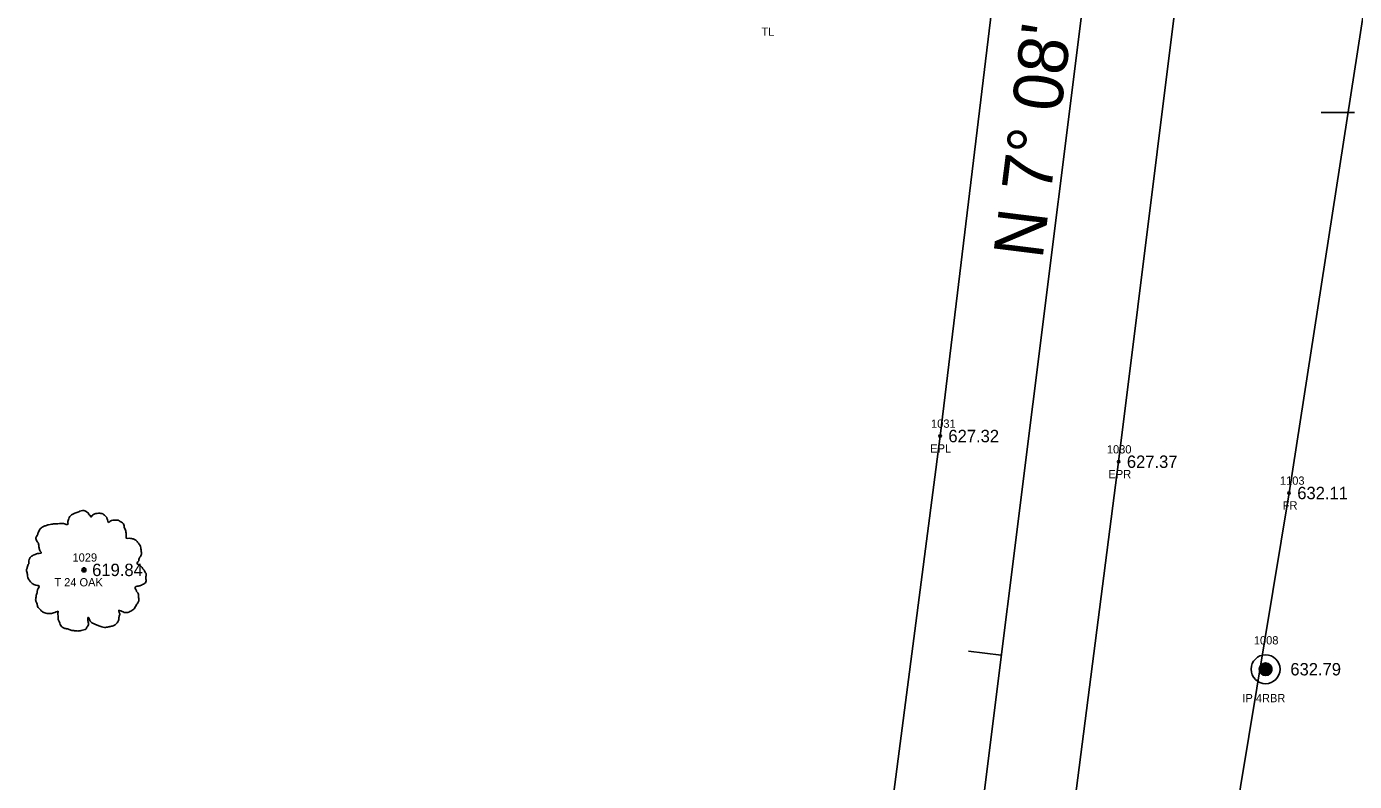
# Model space of a CAD drawing. Extents: x 1694813 to 1696862, y 1086485 to 1091027.
# Drawn here: x 1695761.1 to 1695921.9, y 1087627 to 1087718.4 of the extents above; entities that cross this region are included whole.
import ezdxf

# ---------------------------------------------------------------- set-up
doc = ezdxf.new("R2010")
doc.units = 0
for name, color, linetype in [('RD_EX_DV_Prop_txCode', 7, 'Continuous'), ('RD_EX_DV_PropPin', 7, 'Continuous'), ('RD_EX_Fence_Other', 7, 'Continuous'), ('RD_EX_Fence_Other_txCode', 7, 'Continuous'), ('RD_EX_Road', 7, 'Continuous'), ('RD_EX_Road_txCode', 7, 'Continuous'), ('RD_EX_TX_DV_Prop_ELEV', 7, 'Continuous'), ('RD_EX_TX_Fence_Other_ELEV', 7, 'Continuous'), ('RD_EX_TX_Road_ELEV', 7, 'Continuous'), ('RD_EX_TX_VEG_ELEV', 7, 'Continuous'), ('RD_EX_UT', 7, 'Continuous'), ('RD_EX_VEG', 7, 'Continuous'), ('RD_EX_VEG_txCode', 7, 'Continuous'), ('RD_HC_Cl', 7, 'Continuous'), ('RD_HC_Data', 7, 'Continuous'), ('RD_HC_Data_Tic', 7, 'Continuous'), ('RD_SMD_Locator', 7, 'Continuous')]:
    doc.layers.add(name, color=color, linetype=linetype)

msp = doc.modelspace()

# ---------------------------------------------------------------- linework, layer by layer
at = {"layer": 'RD_EX_DV_PropPin'}
for p, q in [((1695911.03, 1087639.83), (1695911.03, 1087641.34)), ((1695911.06, 1087639.83), (1695911.06, 1087641.34)), ((1695911.1, 1087639.82), (1695911.1, 1087641.34)), ((1695911.13, 1087639.82), (1695911.13, 1087641.34)), ((1695911.17, 1087639.82), (1695911.17, 1087641.34)), ((1695911.2, 1087639.83), (1695911.2, 1087641.34)), ((1695911.24, 1087639.83), (1695911.24, 1087641.34)), ((1695910.4, 1087640.39), (1695910.4, 1087640.78)), ((1695910.43, 1087640.29), (1695910.43, 1087640.88)), ((1695910.47, 1087640.21), (1695910.47, 1087640.95)), ((1695910.5, 1087640.16), (1695910.5, 1087641.01)), ((1695910.54, 1087640.11), (1695910.54, 1087641.06)), ((1695910.57, 1087640.07), (1695910.57, 1087641.1)), ((1695910.61, 1087640.03), (1695910.61, 1087641.13)), ((1695910.64, 1087640), (1695910.64, 1087641.17)), ((1695910.68, 1087639.97), (1695910.68, 1087641.19)), ((1695910.71, 1087639.95), (1695910.71, 1087641.22)), ((1695910.75, 1087639.93), (1695910.75, 1087641.24)), ((1695910.78, 1087639.91), (1695910.78, 1087641.26)), ((1695910.82, 1087639.89), (1695910.82, 1087641.28)), ((1695910.85, 1087639.88), (1695910.85, 1087641.29)), ((1695910.89, 1087639.86), (1695910.89, 1087641.3)), ((1695910.92, 1087639.85), (1695910.92, 1087641.32)), ((1695910.96, 1087639.84), (1695910.96, 1087641.32)), ((1695910.99, 1087639.84), (1695910.99, 1087641.33)), ((1695911.27, 1087639.84), (1695911.27, 1087641.33)), ((1695911.31, 1087639.84), (1695911.31, 1087641.32)), ((1695911.34, 1087639.85), (1695911.34, 1087641.32)), ((1695911.38, 1087639.86), (1695911.38, 1087641.3)), ((1695911.41, 1087639.88), (1695911.41, 1087641.29)), ((1695911.45, 1087639.89), (1695911.45, 1087641.28)), ((1695911.48, 1087639.91), (1695911.48, 1087641.26)), ((1695911.52, 1087639.93), (1695911.52, 1087641.24)), ((1695911.55, 1087639.95), (1695911.55, 1087641.22)), ((1695911.59, 1087639.97), (1695911.59, 1087641.19)), ((1695911.62, 1087640), (1695911.62, 1087641.17)), ((1695911.66, 1087640.03), (1695911.66, 1087641.13)), ((1695911.69, 1087640.07), (1695911.69, 1087641.1)), ((1695911.73, 1087640.11), (1695911.73, 1087641.06)), ((1695911.76, 1087640.16), (1695911.76, 1087641.01)), ((1695911.8, 1087640.21), (1695911.8, 1087640.95)), ((1695911.83, 1087640.29), (1695911.83, 1087640.88)), ((1695911.87, 1087640.39), (1695911.87, 1087640.78))]:
    msp.add_line(p, q, dxfattribs=at)
for radius in [1.75, 0.761]:
    msp.add_circle((1695911.13, 1087640.58), radius, dxfattribs=at)
at = {"layer": 'RD_EX_Fence_Other'}
msp.add_lwpolyline([(1695896.34, 1087555.36), (1695913.97, 1087661.92), (1695929.73, 1087763.6), (1695939.84, 1087832.07), (1696009.84, 1087821.33)], dxfattribs=at)
at = {"layer": 'RD_EX_Road'}
for points in [[(1695879.87, 1087561.29), (1695893.33, 1087665.71), (1695905.96, 1087767.16), (1695918.66, 1087869.54), (1695930.87, 1087972.82), (1695936.26, 1088023.68), (1695942.14, 1088076.32), (1695948.07, 1088128.17), (1695955.04, 1088181.4), (1695962.88, 1088230.72), (1695971.68, 1088284.64), (1695982.02, 1088336.12), (1695993.28, 1088388.48), (1696018.75, 1088494.48), (1696045.23, 1088599.95), (1696055.72, 1088654.41), (1696060.15, 1088705.35), (1696055.83, 1088758.02), (1696044.01, 1088812.16), (1696026.4, 1088860.33), (1696000.41, 1088911.48), (1695972.46, 1088953.82), (1695939.48, 1088998.73), (1695931.21, 1088992.88)], [(1695858.19, 1087564.9), (1695871.71, 1087668.82), (1695884.5, 1087774.69), (1695887.48, 1087794.2), (1695897.57, 1087873.43), (1695908.92, 1087975.76), (1695914.49, 1088029.24), (1695917.65, 1088054.8), (1695920.27, 1088079.09), (1695926.98, 1088130.26), (1695934.75, 1088185.09), (1695942.15, 1088234.62), (1695951.36, 1088288.06), (1695961.48, 1088338.41), (1695972.86, 1088394.13), (1695998.53, 1088499.67), (1696024.81, 1088603.86), (1696034.83, 1088656.78)]]:
    msp.add_lwpolyline(points, dxfattribs=at)
at = {"layer": 'RD_EX_UT'}
msp.add_line((1695921.88, 1087708.01), (1695917.88, 1087708.01), dxfattribs=at)
at = {"layer": 'RD_EX_VEG'}
for centre, radius in [((1695768, 1087652.61), 0.25), ((1695767.99, 1087652.6), 0.0001)]:
    msp.add_circle(centre, radius, dxfattribs=at)
for points in [[(1695768.13, 1087659.78), (1695767.83, 1087659.81), (1695767.51, 1087659.71), (1695767.26, 1087659.61), (1695767.03, 1087659.53), (1695766.81, 1087659.43), (1695766.51, 1087659.26), (1695766.28, 1087659.06), (1695766.16, 1087658.81), (1695766.11, 1087658.58), (1695766.06, 1087658.31), (1695766.06, 1087658.13), (1695765.93, 1087658.11), (1695765.78, 1087658.13), (1695765.53, 1087658.21), (1695765.28, 1087658.21), (1695765.03, 1087658.21), (1695764.68, 1087658.18), (1695764.33, 1087658.18), (1695764.06, 1087658.13), (1695763.73, 1087658.08), (1695763.36, 1087657.96), (1695763.01, 1087657.83), (1695762.71, 1087657.58), (1695762.46, 1087657.11), (1695762.34, 1087656.76), (1695762.19, 1087656.51), (1695762.34, 1087656.06), (1695762.51, 1087655.71), (1695762.54, 1087655.51), (1695762.61, 1087655.08), (1695762.71, 1087654.86), (1695762.84, 1087654.66), (1695762.76, 1087654.63), (1695762.39, 1087654.58), (1695762.09, 1087654.48), (1695761.66, 1087654.26), (1695761.44, 1087654.03), (1695761.34, 1087653.71), (1695761.31, 1087653.36), (1695761.21, 1087653.16), (1695761.14, 1087652.88), (1695761.11, 1087652.81), (1695761.06, 1087652.49), (1695761.16, 1087652.04), (1695761.19, 1087651.69), (1695761.31, 1087651.46), (1695761.46, 1087651.29), (1695761.64, 1087651.04), (1695762.04, 1087650.81), (1695762.36, 1087650.71), (1695762.56, 1087650.69), (1695762.39, 1087650.19), (1695762.34, 1087649.84), (1695762.21, 1087649.44), (1695762.21, 1087649.36), (1695762.16, 1087648.89), (1695762.31, 1087648.56), (1695762.39, 1087648.19), (1695762.56, 1087647.96), (1695762.84, 1087647.66), (1695763.16, 1087647.44), (1695763.66, 1087647.31), (1695764.06, 1087647.34), (1695764.63, 1087647.51), (1695764.88, 1087647.59), (1695764.86, 1087647.41), (1695764.88, 1087647.04), (1695764.88, 1087646.61), (1695765.03, 1087646.29), (1695765.13, 1087646.01), (1695765.28, 1087645.76), (1695765.61, 1087645.54), (1695766.01, 1087645.46), (1695766.43, 1087645.31), (1695766.88, 1087645.24), (1695767.38, 1087645.21), (1695767.98, 1087645.36), (1695768.26, 1087645.49), (1695768.36, 1087645.66), (1695768.56, 1087646.04), (1695768.51, 1087646.26), (1695768.53, 1087646.86), (1695768.63, 1087646.69), (1695768.81, 1087646.34), (1695769.31, 1087646.04), (1695769.71, 1087645.86), (1695770.18, 1087645.71), (1695770.48, 1087645.64), (1695770.96, 1087645.71), (1695771.33, 1087645.79), (1695771.71, 1087645.91), (1695772.01, 1087646.19), (1695772.18, 1087646.46), (1695772.23, 1087646.74), (1695772.31, 1087647.11), (1695772.36, 1087647.29)], [(1695772.36, 1087647.29), (1695772.28, 1087647.46), (1695772.23, 1087647.71), (1695772.31, 1087647.69), (1695772.48, 1087647.64), (1695772.76, 1087647.51), (1695772.98, 1087647.44), (1695773.31, 1087647.46), (1695773.58, 1087647.56), (1695774.03, 1087647.84), (1695774.31, 1087648.31), (1695774.58, 1087648.71), (1695774.66, 1087649.04), (1695774.61, 1087649.26), (1695774.58, 1087649.76), (1695774.38, 1087650.01), (1695774.33, 1087650.14), (1695774.23, 1087650.54), (1695774.31, 1087650.59), (1695774.58, 1087650.64), (1695774.96, 1087650.76), (1695775.23, 1087650.89), (1695775.45, 1087651.06), (1695775.53, 1087651.29), (1695775.5, 1087651.69), (1695775.55, 1087652.09), (1695775.48, 1087652.24), (1695775.38, 1087652.39), (1695775.3, 1087652.59), (1695775.15, 1087652.73), (1695775.06, 1087652.88), (1695774.96, 1087652.98), (1695774.83, 1087653.13), (1695774.66, 1087653.26), (1695774.51, 1087653.31), (1695774.46, 1087653.46), (1695774.61, 1087653.66), (1695774.66, 1087653.76), (1695774.68, 1087653.98), (1695774.91, 1087654.33), (1695774.96, 1087654.73), (1695774.91, 1087655.16), (1695774.86, 1087655.43), (1695774.71, 1087655.71), (1695774.51, 1087655.96), (1695774.38, 1087656.13), (1695774.21, 1087656.26), (1695773.88, 1087656.38), (1695773.63, 1087656.43), (1695773.28, 1087656.43), (1695773.08, 1087656.48), (1695773.11, 1087656.53), (1695773.11, 1087656.68), (1695773.11, 1087656.96), (1695773.03, 1087657.41), (1695772.88, 1087657.91), (1695772.88, 1087657.93), (1695772.78, 1087658.18), (1695772.56, 1087658.38), (1695772.38, 1087658.48), (1695772.18, 1087658.61), (1695771.93, 1087658.63), (1695771.63, 1087658.63), (1695771.36, 1087658.58), (1695771.16, 1087658.48), (1695770.98, 1087658.36), (1695770.91, 1087658.51), (1695770.81, 1087658.81), (1695770.76, 1087658.96), (1695770.61, 1087659.13), (1695770.38, 1087659.33), (1695769.93, 1087659.46), (1695769.31, 1087659.38), (1695769.01, 1087659.18), (1695768.86, 1087659.01), (1695768.81, 1087659.13), (1695768.61, 1087659.33), (1695768.51, 1087659.51), (1695768.33, 1087659.63), (1695768.18, 1087659.73), (1695768.08, 1087659.78)]]:
    msp.add_spline(points, degree=3, dxfattribs=at)
at = {"layer": 'RD_HC_Cl'}
msp.add_line((1695866.12, 1087538.58), (1695910.69, 1087894.29), dxfattribs=at)
at = {"layer": 'RD_HC_Data_Tic'}
msp.add_line((1695879.11, 1087642.27), (1695875.14, 1087642.76), dxfattribs=at)
at = {"layer": 'RD_SMD_Locator'}
for centre in [(1695871.71, 1087668.82), (1695893.33, 1087665.71), (1695913.97, 1087661.92), (1695768, 1087652.61), (1695911.13, 1087640.58)]:
    msp.add_circle(centre, 0.15, dxfattribs=at)

# ---------------------------------------------------------------- texts
at = {"layer": 'RD_EX_DV_Prop_txCode'}
for s, p in [('1008', (1695909.71, 1087643.58)), ('IP 4RBR', (1695908.32, 1087636.58))]:
    msp.add_text(s, height=1, dxfattribs=at).set_placement(p)
at = {"layer": 'RD_EX_Fence_Other_txCode'}
for s, p in [('1103', (1695912.87, 1087662.92)), ('FR', (1695913.21, 1087659.92))]:
    msp.add_text(s, height=1, dxfattribs=at).set_placement(p)
at = {"layer": 'RD_EX_Road_txCode'}
for s, p in [('1031', (1695870.61, 1087669.82)), ('EPL', (1695870.51, 1087666.82)), ('1030', (1695891.91, 1087666.71)), ('EPR', (1695892.1, 1087663.71))]:
    msp.add_text(s, height=1, dxfattribs=at).set_placement(p)
at = {"layer": 'RD_EX_TX_DV_Prop_ELEV'}
msp.add_text('632.79', height=1.5, dxfattribs=at).set_placement((1695914.13, 1087639.83))
at = {"layer": 'RD_EX_TX_Fence_Other_ELEV'}
msp.add_text('632.11', height=1.5, dxfattribs=at).set_placement((1695914.97, 1087661.17))
at = {"layer": 'RD_EX_TX_Road_ELEV'}
for s, p in [('627.32', (1695872.71, 1087668.07)), ('627.37', (1695894.33, 1087664.96))]:
    msp.add_text(s, height=1.5, dxfattribs=at).set_placement(p)
at = {"layer": 'RD_EX_TX_VEG_ELEV'}
msp.add_text('619.84', height=1.5, dxfattribs=at).set_placement((1695769, 1087651.86))
at = {"layer": 'RD_EX_VEG_txCode'}
for s, p in [('TL', (1695850.07, 1087717.29)), ('1029', (1695766.62, 1087653.61)), ('T 24 OAK', (1695764.42, 1087650.61))]:
    msp.add_text(s, height=1, dxfattribs=at).set_placement(p)
at = {"layer": 'RD_HC_Data'}
msp.add_text('N 7%%d 08\' 27" E', height=6, rotation=82.8592, dxfattribs=at).set_placement((1695884.1, 1087690.14))

doc.saveas('drawing.dxf')
